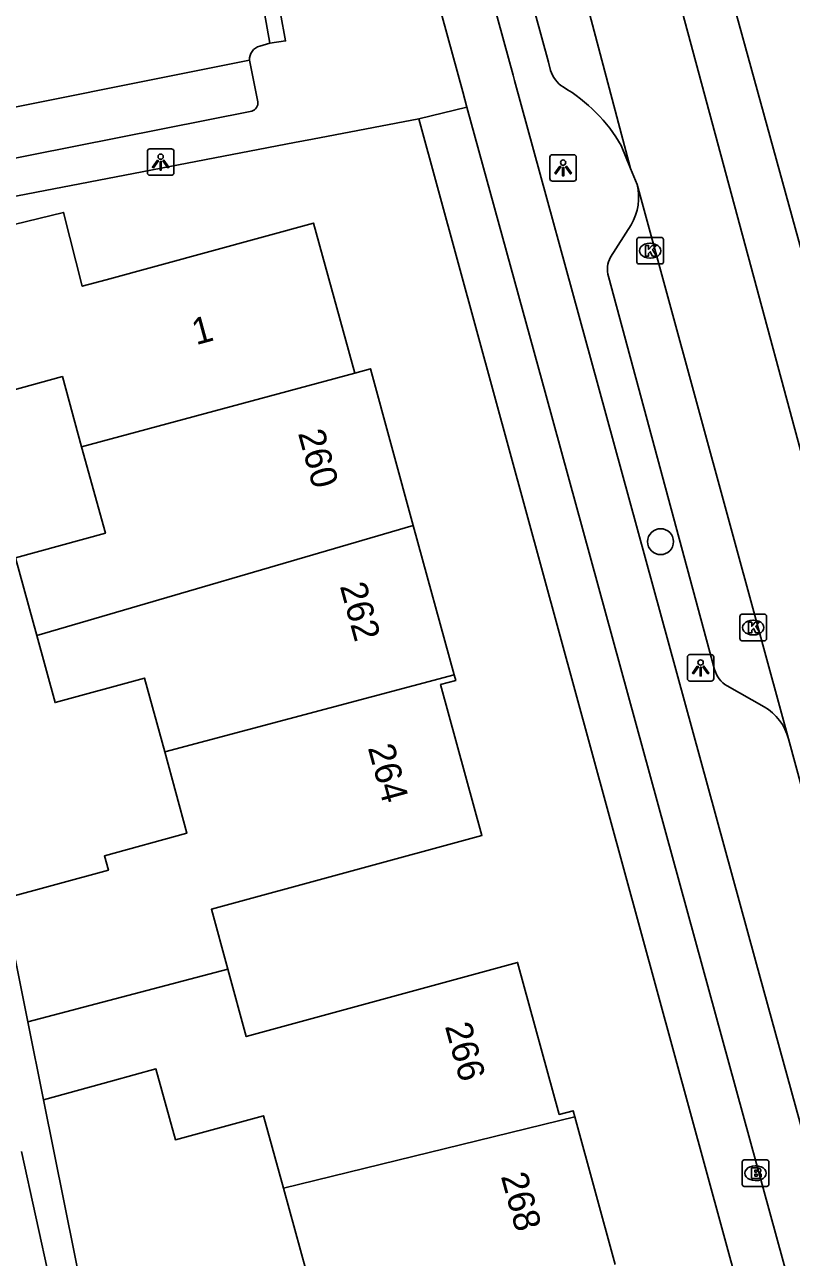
# Model space of a CAD drawing. Extents: x 162250 to 162654, y 380744 to 381605.
# Drawn here: x 162533.18 to 162562.08, y 381100.24 to 381146.75 of the extents above; entities that cross this region are included whole.
import ezdxf

# ---------------------------------------------------------------- set-up
doc = ezdxf.new("R2010")
doc.units = 0
for name, color, linetype in [('IMGEO_Boom', 7, 'Continuous'), ('IMGEO_Brandkraan', 7, 'Continuous'), ('IMGEO_Fietspad_gesloten', 7, 'Continuous'), ('IMGEO_Kolk', 7, 'Continuous'), ('IMGEO_Lichtpunt', 7, 'Continuous'), ('IMGEO_Pand', 7, 'Continuous'), ('IMGEO_Pand_nummerreeks', 7, 'Continuous'), ('IMGEO_Parkeervlak_open', 7, 'Continuous'), ('IMGEO_Rijbaan_regionaal_gesloten', 7, 'Continuous'), ('IMGEO_Voetpad_open', 7, 'Continuous'), ('IMGEO_Woonerf_open', 7, 'Continuous')]:
    doc.layers.add(name, color=color, linetype=linetype)

msp = doc.modelspace()

# ---------------------------------------------------------------- linework, layer by layer
at = {"layer": 'IMGEO_Boom'}
msp.add_circle((162557.155, 381127.244), 0.489, dxfattribs=at)
at = {"layer": 'IMGEO_Brandkraan'}
for p, q in [((162560.235, 381102.99), (162560.235, 381103.842)), ((162560.31, 381103.916), (162561.162, 381103.916)), ((162560.723, 381103.696), (162560.748, 381103.696)), ((162561.236, 381103.842), (162561.236, 381102.99)), ((162560.746, 381103.136), (162560.721, 381103.136)), ((162561.162, 381102.916), (162560.31, 381102.916))]:
    msp.add_line(p, q, dxfattribs=at)
for points in [[(162560.235, 381102.99), (162560.235, 381103.842)], [(162560.31, 381103.916), (162561.162, 381103.916)], [(162560.583, 381103.616), (162560.583, 381103.216), (162560.796, 381103.216)], [(162560.814, 381103.616), (162560.583, 381103.616)], [(162561.236, 381103.842), (162561.236, 381102.99)], [(162560.762, 381103.535), (162560.708, 381103.535), (162560.708, 381103.459)], [(162560.708, 381103.459), (162560.761, 381103.459)], [(162560.77, 381103.383), (162560.708, 381103.383), (162560.708, 381103.302)], [(162560.708, 381103.302), (162560.77, 381103.302)], [(162561.162, 381102.916), (162560.31, 381102.916)]]:
    msp.add_lwpolyline(points, dxfattribs=at)
for centre, radius, start, end in [((162560.312, 381103.84), 0.0765, 91.552, 178.448), ((162560.312, 381103.84), 0.0765, 91.552, 178.448), ((162560.818, 381103.471), 0.145, 59.4692, 91.5367), ((162560.843, 381103.518), 0.0922, 285.5137, 58.1501), ((162561.16, 381103.84), 0.0765, 1.552, 88.448), ((162561.16, 381103.84), 0.0765, 1.552, 88.448), ((162560.763, 381103.497), 0.0379, 267.8285, 90.9355), ((162560.771, 381103.342), 0.0404, 269.8759, 90.5077), ((162560.802, 381103.467), 0.251, 268.6676, 293.5347), ((162560.848, 381103.326), 0.105, 301.3115, 78.989), ((162560.312, 381102.992), 0.0765, 181.552, 268.448), ((162560.312, 381102.992), 0.0765, 181.552, 268.448), ((162561.16, 381102.992), 0.0765, 271.552, 358.448), ((162561.16, 381102.992), 0.0765, 271.552, 358.448)]:
    msp.add_arc(centre, radius, start, end, dxfattribs=at)
for centre, major_axis, ratio, start_param, end_param in [((162560.722, 381103.416), (-0.387, 0.002), 0.722429, 4.712389, 7.853982), ((162560.747, 381103.416), (-0.39, 0.002), 0.717154, 1.570796, 4.712389)]:
    msp.add_ellipse(centre, major_axis=major_axis, ratio=ratio, start_param=start_param, end_param=end_param, dxfattribs=at)
at = {"layer": 'IMGEO_Fietspad_gesloten'}
for points in [[(162536.398, 381200.372), (162539.144, 381190.342), (162540.943, 381183.77), (162548.984, 381154.395), (162551.592, 381144.84), (162551.645, 381144.647), (162554.806, 381133.124), (162560.736, 381111.446), (162562.992, 381103.198), (162573.052, 381066.398), (162577.335, 381050.801), (162584.526, 381024.553), (162587.309, 381014.367), (162588.433, 381010.254), (162590.219, 381003.716), (162603.154, 380956.316), (162606.977, 380942.372), (162608.338, 380937.386), (162611.747, 380924.889), (162613.149, 380919.833), (162613.482, 380918.571)], [(162549.852, 381143.643), (162549.695, 381144.216), (162547.143, 381153.533)], [(162626.231, 380864.638), (162619.54, 380889.111), (162611.456, 380918.623), (162600.985, 380956.955), (162588.336, 381003.241), (162586.64, 381009.407), (162585.413, 381013.87), (162582.804, 381023.355), (162575.392, 381050.363), (162571.085, 381066.091), (162561.27, 381101.934), (162558.72, 381111.249), (162552.836, 381132.744), (162549.852, 381143.643)]]:
    msp.add_lwpolyline(points, dxfattribs=at)
at = {"layer": 'IMGEO_Kolk'}
for p, q in [((162556.258, 381137.794), (162556.258, 381138.646)), ((162556.333, 381138.72), (162557.185, 381138.72)), ((162556.746, 381138.5), (162556.771, 381138.5)), ((162557.259, 381138.646), (162557.259, 381137.794)), ((162557.185, 381137.72), (162556.333, 381137.72)), ((162556.769, 381137.94), (162556.744, 381137.94)), ((162560.223, 381124.503), (162561.075, 381124.503)), ((162560.148, 381123.577), (162560.148, 381124.429)), ((162560.636, 381124.283), (162560.661, 381124.283)), ((162561.149, 381124.429), (162561.149, 381123.577)), ((162560.659, 381123.723), (162560.634, 381123.723)), ((162561.075, 381123.503), (162560.223, 381123.503))]:
    msp.add_line(p, q, dxfattribs=at)
for points in [[(162556.258, 381137.794), (162556.258, 381138.646)], [(162556.333, 381138.72), (162557.185, 381138.72)], [(162557.259, 381138.646), (162557.259, 381137.794)], [(162556.579, 381138.42), (162556.702, 381138.42), (162556.702, 381138.269), (162556.832, 381138.42), (162556.996, 381138.42), (162556.85, 381138.269), (162557.003, 381138.02), (162556.851, 381138.02), (162556.766, 381138.184), (162556.702, 381138.117), (162556.702, 381138.02), (162556.579, 381138.02), (162556.579, 381138.42)], [(162557.185, 381137.72), (162556.333, 381137.72)], [(162560.223, 381124.503), (162561.075, 381124.503)], [(162560.148, 381123.577), (162560.148, 381124.429)], [(162560.469, 381124.203), (162560.592, 381124.203), (162560.592, 381124.052), (162560.722, 381124.203), (162560.886, 381124.203), (162560.74, 381124.052), (162560.893, 381123.803), (162560.741, 381123.803), (162560.656, 381123.967), (162560.592, 381123.9), (162560.592, 381123.803), (162560.469, 381123.803), (162560.469, 381124.203)], [(162561.149, 381124.429), (162561.149, 381123.577)], [(162561.075, 381123.503), (162560.223, 381123.503)]]:
    msp.add_lwpolyline(points, dxfattribs=at)
for centre, start, end in [((162556.335, 381138.644), 91.552, 178.448), ((162556.335, 381138.644), 91.552, 178.448), ((162557.183, 381138.644), 1.552, 88.448), ((162557.183, 381138.644), 1.552, 88.448), ((162556.335, 381137.796), 181.552, 268.448), ((162556.335, 381137.796), 181.552, 268.448), ((162557.183, 381137.796), 271.552, 358.448), ((162557.183, 381137.796), 271.552, 358.448), ((162560.225, 381124.427), 91.552, 178.448), ((162560.225, 381124.427), 91.552, 178.448), ((162561.073, 381124.427), 1.552, 88.448), ((162561.073, 381124.427), 1.552, 88.448), ((162560.225, 381123.579), 181.552, 268.448), ((162560.225, 381123.579), 181.552, 268.448), ((162561.073, 381123.579), 271.552, 358.448), ((162561.073, 381123.579), 271.552, 358.448)]:
    msp.add_arc(centre, 0.0765, start, end, dxfattribs=at)
for centre, major_axis, ratio, start_param, end_param in [((162556.745, 381138.22), (-0.387, 0.002), 0.722429, 4.712389, 7.853982), ((162556.77, 381138.22), (-0.39, 0.002), 0.717154, 1.570796, 4.712389), ((162560.635, 381124.003), (-0.387, 0.002), 0.722429, 4.712389, 7.853982), ((162560.66, 381124.003), (-0.39, 0.002), 0.717154, 1.570796, 4.712389)]:
    msp.add_ellipse(centre, major_axis=major_axis, ratio=ratio, start_param=start_param, end_param=end_param, dxfattribs=at)
at = {"layer": 'IMGEO_Lichtpunt'}
for p, q in [((162537.805, 381141.971), (162537.805, 381141.164)), ((162537.805, 381141.971), (162537.805, 381141.164)), ((162538.707, 381142.066), (162537.899, 381142.066)), ((162538.707, 381142.066), (162537.899, 381142.066)), ((162538.801, 381141.164), (162538.801, 381141.971)), ((162538.801, 381141.164), (162538.801, 381141.971)), ((162552.98, 381141.747), (162552.98, 381140.94)), ((162552.98, 381141.747), (162552.98, 381140.94)), ((162553.882, 381141.842), (162553.074, 381141.842)), ((162553.882, 381141.842), (162553.074, 381141.842)), ((162553.976, 381140.94), (162553.976, 381141.747)), ((162553.976, 381140.94), (162553.976, 381141.747)), ((162537.899, 381141.07), (162538.707, 381141.07)), ((162537.899, 381141.07), (162538.707, 381141.07)), ((162553.074, 381140.846), (162553.882, 381140.846)), ((162553.074, 381140.846), (162553.882, 381140.846)), ((162558.165, 381122.886), (162558.165, 381122.079)), ((162558.165, 381122.886), (162558.165, 381122.079)), ((162559.067, 381122.981), (162558.259, 381122.981)), ((162559.067, 381122.981), (162558.259, 381122.981)), ((162559.161, 381122.079), (162559.161, 381122.886)), ((162559.161, 381122.079), (162559.161, 381122.886)), ((162558.259, 381121.985), (162559.067, 381121.985)), ((162558.259, 381121.985), (162559.067, 381121.985))]:
    msp.add_line(p, q, dxfattribs=at)
for points in [[(162538.179, 381141.635), (162538.218, 381141.607), (162538.03, 381141.345), (162537.992, 381141.372), (162538.179, 381141.635)], [(162538.281, 381141.587), (162538.328, 381141.587), (162538.328, 381141.265), (162538.281, 381141.265), (162538.281, 381141.587)], [(162538.391, 381141.607), (162538.429, 381141.634), (162538.616, 381141.372), (162538.577, 381141.344), (162538.391, 381141.607)], [(162553.354, 381141.411), (162553.393, 381141.383), (162553.205, 381141.121), (162553.167, 381141.148), (162553.354, 381141.411)], [(162553.456, 381141.363), (162553.503, 381141.363), (162553.503, 381141.041), (162553.456, 381141.041), (162553.456, 381141.363)], [(162553.566, 381141.383), (162553.604, 381141.41), (162553.791, 381141.148), (162553.752, 381141.12), (162553.566, 381141.383)], [(162558.539, 381122.55), (162558.578, 381122.522), (162558.39, 381122.26), (162558.352, 381122.287), (162558.539, 381122.55)], [(162558.641, 381122.502), (162558.688, 381122.502), (162558.688, 381122.18), (162558.641, 381122.18), (162558.641, 381122.502)], [(162558.751, 381122.522), (162558.789, 381122.549), (162558.976, 381122.287), (162558.937, 381122.259), (162558.751, 381122.522)]]:
    msp.add_lwpolyline(points, dxfattribs=at)
for centre in [(162538.304, 381141.769), (162553.479, 381141.545), (162558.664, 381122.684)]:
    msp.add_circle(centre, 0.0994, dxfattribs=at)
for centre, start, end in [((162537.899, 381141.971), 90, 180), ((162537.899, 381141.971), 90, 180), ((162538.707, 381141.971), 0, 90), ((162538.707, 381141.971), 0, 90), ((162553.074, 381141.747), 90, 180), ((162553.074, 381141.747), 90, 180), ((162553.882, 381141.747), 0, 90), ((162553.882, 381141.747), 0, 90), ((162537.899, 381141.164), 180, 270), ((162537.899, 381141.164), 180, 270), ((162538.707, 381141.164), 270, 0), ((162538.707, 381141.164), 270, 360), ((162553.074, 381140.94), 180, 270), ((162553.074, 381140.94), 180, 270), ((162553.882, 381140.94), 270, 0), ((162553.882, 381140.94), 270, 360), ((162558.259, 381122.886), 90, 180), ((162558.259, 381122.886), 90, 180), ((162559.067, 381122.886), 0, 90), ((162559.067, 381122.886), 0, 90), ((162558.259, 381122.079), 180, 270), ((162558.259, 381122.079), 180, 270), ((162559.067, 381122.079), 270, 0), ((162559.067, 381122.079), 270, 360)]:
    msp.add_arc(centre, 0.0946, start, end, dxfattribs=at)
at = {"layer": 'IMGEO_Pand'}
for points in [[(162545.62, 381133.605), (162544.072, 381139.266), (162536.248, 381137.126), (162535.347, 381136.88), (162534.642, 381139.666), (162530.49, 381138.654), (162530.258, 381138.598), (162530.993, 381135.689), (162530.58, 381135.576), (162530.368, 381136.65), (162527.076, 381136.002)], [(162528.246, 381130.613), (162531.429, 381131.239), (162531.174, 381132.533), (162534.602, 381133.471), (162535.325, 381130.827)], [(162535.325, 381130.827), (162545.62, 381133.605)], [(162547.83, 381127.859), (162546.214, 381133.765), (162545.62, 381133.605)], [(162535.325, 381130.827), (162536.219, 381127.558), (162532.83, 381126.631), (162533.63, 381123.706)], [(162533.63, 381123.706), (162547.83, 381127.859)], [(162549.374, 381122.215), (162547.83, 381127.859)], [(162533.63, 381123.706), (162534.322, 381121.173), (162537.695, 381122.096), (162538.456, 381119.316)], [(162549.374, 381122.215), (162538.456, 381119.316)], [(162540.837, 381111.114), (162540.22, 381113.372), (162550.416, 381116.161), (162548.86, 381121.849), (162549.431, 381122.005), (162549.374, 381122.215)], [(162538.456, 381119.316), (162539.296, 381116.244), (162536.185, 381115.393), (162536.335, 381114.848), (162532.362, 381113.762)], [(162533.293, 381109.132), (162532.362, 381113.762)], [(162533.293, 381109.132), (162540.837, 381111.114)], [(162553.915, 381105.543), (162553.852, 381105.774), (162553.33, 381105.631), (162551.761, 381111.366), (162541.533, 381108.569), (162540.837, 381111.114)], [(162533.885, 381106.188), (162533.293, 381109.132)], [(162542.936, 381102.845), (162542.186, 381105.585), (162538.858, 381104.675), (162538.126, 381107.348), (162536.488, 381106.9), (162533.885, 381106.188)], [(162553.915, 381105.543), (162542.936, 381102.845)], [(162555.439, 381099.973), (162553.915, 381105.543)], [(162542.936, 381102.845), (162543.786, 381099.737), (162540.528, 381098.846), (162540.717, 381098.155)]]:
    msp.add_lwpolyline(points, dxfattribs=at)
at = {"layer": 'IMGEO_Parkeervlak_open'}
for points in [[(162530.009, 381141.165), (162529.651, 381143.002), (162541.654, 381145.406)], [(162555.263, 381137.978), (162556.045, 381139.198)], [(162559.191, 381122.421), (162555.188, 381137.246)], [(162561.057, 381121.014), (162559.661, 381121.801)]]:
    msp.add_lwpolyline(points, dxfattribs=at)
for centre, radius, start, end in [((162554.276, 381140.235), 2.05, 329.6254, 13.8308), ((162556.075, 381137.525), 0.929, 150.8304, 197.4694), ((162560.2, 381122.698), 1.046, 195.3393, 238.9896), ((162559.995, 381119.243), 2.065, 15.8299, 59.0547)]:
    msp.add_arc(centre, radius, start, end, dxfattribs=at)
at = {"layer": 'IMGEO_Rijbaan_regionaal_gesloten'}
for points in [[(162540.124, 381201.475), (162556.025, 381141.32)], [(162545.104, 381200.933), (162546.555, 381196.038), (162562.469, 381138.221), (162569.845, 381112.873)], [(162567.409, 381112.237), (162544.792, 381196.117), (162543.648, 381200.38)], [(162553.008, 381145.025), (162552.925, 381145.33), (162550.374, 381154.672), (162550.34, 381154.796), (162542.98, 381181.61)], [(162556.025, 381141.32), (162555.673, 381142.187)], [(162556.025, 381141.32), (162556.267, 381140.725)], [(162556.267, 381140.725), (162561.982, 381119.806)], [(162561.982, 381119.806), (162563.768, 381113.225), (162565.639, 381106.468)]]:
    msp.add_lwpolyline(points, dxfattribs=at)
for centre, radius, start, end in [((162554.076, 381145.344), 1.115, 196.6042, 237.721), ((162550.293, 381139.052), 6.227, 30.2269, 59.2009)]:
    msp.add_arc(centre, radius, start, end, dxfattribs=at)
at = {"layer": 'IMGEO_Voetpad_open'}
for points in [[(162541.689, 381150.159), (162542.254, 381150.28), (162543.014, 381146.137), (162542.424, 381146.057)], [(162542.424, 381146.057), (162542.043, 381145.939)], [(162541.654, 381145.406), (162541.968, 381143.837)], [(162549.852, 381143.643), (162548.044, 381143.201)], [(162505.307, 381134.801), (162526.506, 381138.986), (162526.734, 381139.031), (162529.938, 381139.71), (162530.217, 381139.774), (162543.35, 381142.299), (162544.023, 381142.428), (162548.044, 381143.201)], [(162541.744, 381143.487), (162530.009, 381141.165)], [(162548.044, 381143.201), (162550.23, 381135.191), (162568.771, 381067.243), (162583.561, 381013.383), (162590.707, 380987.36)], [(162548.818, 381031.958), (162533.885, 381106.188)], [(162533.059, 381104.234), (162534.676, 381096.835)]]:
    msp.add_lwpolyline(points, dxfattribs=at)
for centre, radius, start, end in [((162542.168, 381145.439), 0.515, 104.0532, 183.7006), ((162541.644, 381143.798), 0.327, 287.8672, 6.8943)]:
    msp.add_arc(centre, radius, start, end, dxfattribs=at)
at = {"layer": 'IMGEO_Woonerf_open'}
msp.add_lwpolyline([(162541.689, 381150.159), (162542.424, 381146.057)], dxfattribs=at)

# ---------------------------------------------------------------- texts
at = {"layer": 'IMGEO_Pand_nummerreeks'}
for s, rotation, p in [('1', 15.2961, (162539.639, 381134.653)), ('260', 285.2992, (162543.477, 381131.338)), ('262', 285.2992, (162545.055, 381125.569)), ('264', 285.2978, (162546.11, 381119.469)), ('266', 285.3008, (162549.017, 381108.962)), ('268', 285.2978, (162551.127, 381103.302))]:
    msp.add_text(s, height=1, rotation=rotation, dxfattribs=at).set_placement(p)

doc.saveas('drawing.dxf')
